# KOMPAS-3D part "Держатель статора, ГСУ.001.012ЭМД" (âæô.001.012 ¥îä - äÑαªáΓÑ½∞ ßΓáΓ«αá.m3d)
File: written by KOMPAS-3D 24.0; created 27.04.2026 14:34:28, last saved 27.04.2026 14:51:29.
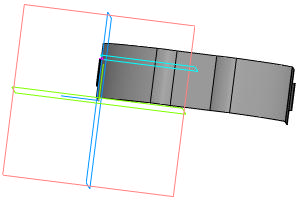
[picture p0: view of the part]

Document properties: Автор: USG_411; Полное имя файла: C:\Users\USG_411.STUD\Desktop\ГМ2704_411-23\Двигатель мясорубки\ГСУ.001.012 ЭМД - Держатель статора.m3d

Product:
- Part/product: Держатель статора  | designation ГСУ.001.012ЭМД
    Масса: 0.003633

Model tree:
1. Эскиз:1
2. Элемент выдавливания:1
     Толщина стенки 1 = 0.25; Расстояние 1 = 16
3. Смещенная плоскость:1  (with: Грань.Элемент выдавливания:1)
     Расстояние = 4
4. Эскиз:2  (with: Ребро.Элемент выдавливания:1)
5. Элемент выдавливания:2
     Расстояние 2 = 8
6. Зеркальное отражение:1
7. Экземпляр ( 1 )
8. Экземпляр ( 2 )
9. Тело 1  (with: Грань.Элемент выдавливания:1)

Expressions: 55/2; 11.8/2
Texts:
  ГСУ.001.012
  ГСУ.001.012 ЭМД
